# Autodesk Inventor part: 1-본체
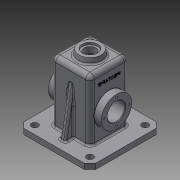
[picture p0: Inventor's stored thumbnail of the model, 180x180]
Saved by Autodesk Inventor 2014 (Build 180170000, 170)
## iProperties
Created: 2016-02
Part Number: 1-본체
Material: 일반
Document SubType Name: Modeling
Designer: Administrator
Density: 1 g/cm^3
Appearance: 기본값
Author: Administrator
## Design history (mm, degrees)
node "작업 평면1"
sketch "스케치1"
  geometry: L1 (-65, 65)-(65, 65); L2 (65, 65)-(65, -65); L3 (65, -65)-(-65, -65); L4 (-65, -65)-(-65, 65); 3 further points
  constraints: 8 end point, 2 midpoint, 2 parallel, 1 horizontal, 1 horizontal alignment, 1 perpendicular, 1 vertical alignment
  dimensions: "d1" = 130 distance of L1.start L1.end; "d2" = 130 distance of L1.end L2.end
extrude "돌출1" new body sketch "스케치1" distance "d3" = 10; taper "d4" = 0 deg
sketch "스케치2"
  geometry: L1 (-35, 35)-(35, 35); L2 (35, 35)-(35, -35); L3 (35, -35)-(-35, -35); L4 (-35, -35)-(-35, 35); L5 (30, 30)-(-30, 30); L6 (-30, 30)-(-30, -30); L7 (-30, -30)-(30, -30); L8 (30, -30)-(30, 30); 3 further points
  constraints: 16 end point, 4 parallel, 3 perpendicular, 2 midpoint, 1 horizontal, 1 horizontal alignment, 1 vertical alignment, 3 other
  dimensions: "d5" = 70 distance of L1.start L1.end; "d8" = 5 distance between parallel lines of L2 L8
extrude "돌출2" join sketch "스케치2" distance "d6" = 120; taper "d7" = 0 deg
extrude "돌출3" cut sketch "스케치2" distance "d9" = 115; taper "d10" = 0 deg
sketch "스케치3"
  geometry: C1 r 27.5 at (0, 0); 1 further point
  constraints: 1 centre point, 1 coincident
  dimensions: "d11" = 55 diameter of C1
extrude "돌출4" join sketch "스케치3" stored distance "d12" = 96; taper "d13" = 0 deg
hole "구멍1" diameter "d16" = 32; stored, may be unused: countersink angle "d20" = 90 deg, drill point angle "d22" = 118 deg; dims "d14" = 10, "d15" = 10, "d17" = 6, "d18" = 4, "d19" = 2, "d21" = 8
sketch "스케치6" dims "d32" = 45
  geometry: 3 further points
  constraints: 2 horizontal alignment, 1 coincident, 2 other
hole "구멍2" sketch "스케치6" at (-22.5, 0) diameter "d33" = 3.242; stored, may be unused: countersink angle "d37" = 90 deg, drill point angle "d39" = 118 deg; dims "d34" = 8, "d35" = 4, "d36" = 2, "d38" = 10
sketch "스케치4"
  geometry: L1 (30, -55)-(30, 60) reference; L2 (-30, -55)-(-30, 60) reference; L3 (30, 27.5)-(-30, 27.5); L4 (-30, 27.5)-(-23, 20.5); L5 (-23, 20.5)-(-23, 0); L6 (-23, 0)-(23, 0); L7 (23, 0)-(23, 20.5); L8 (23, 20.5)-(30, 27.5); 2 further points
  constraints: 12 end point, 4 perpendicular, 2 point on line, 1 coincident, 1 midpoint
  dimensions: "d23" = 135 deg angle of L1 L8; "d24" = 135 deg angle of L2 L4; "d25" = 7 distance between parallel lines of L7 L1; "d26" = 55 diameter of L3 L6
revolve "회전1" sketch "스케치4" stored, may be unused: angle "d27" = 90 deg
node "작업 평면2"
sketch "스케치5"
  geometry: C1 r 20 at (0, 0); 1 further point
  constraints: 1 centre point, 1 coincident
  dimensions: "d29" = 40 diameter of C1
extrude "돌출5" join sketch "스케치5" stored distance "d30" = 96; taper "d31" = 10 deg
hole "구멍3" diameter "d45" = 21; stored, may be unused: countersink angle "d49" = 90 deg, drill point angle "d51" = 0 deg; dims "d43" = 10, "d44" = 10, "d46" = 8, "d47" = 28, "d48" = 4, "d50" = 10
sketch "스케치7"
  geometry: L1 (35, 65)-(35, -45) reference; L2 (35, -45)-(65, -45) reference; L3 (65, -45)-(65, -55) reference; L4 (65, -55)-(30, -55) reference; L5 (30, -55)-(30, 60) reference; L6 (30, 60)-(10.5, 60) reference; L7 (10.5, 60)-(10.5, 71) reference; L8 (10.5, 71)-(14, 71) reference; L9 (14, 71)-(14, 75) reference; L10 (14, 75)-(20, 75) reference; L11 (20, 75)-(21.763, 65) reference; L12 (21.763, 65)-(35, 65) reference; L13 (-30, -55)-(-65, -55) reference; L14 (-65, -55)-(-65, -45) reference; L15 (-65, -45)-(-35, -45) reference; L16 (-35, -45)-(-35, 65) reference; L17 (-35, 65)-(-21.763, 65) reference; L18 (-21.763, 65)-(-20, 75) reference; L19 (-20, 75)-(-14, 75) reference; L20 (-14, 75)-(-14, 71) reference; L21 (-14, 71)-(-10.5, 71) reference; L22 (-10.5, 71)-(-10.5, 60) reference; L23 (-10.5, 60)-(-30, 60) reference; L24 (-30, 60)-(-30, -55) reference; L25 (-50, -45)-(-35, 40.069); L26 (35, 40.069)-(50, -45); 1 further point
  constraints: 4 end point, 2 midpoint, 2 point on line
  dimensions: "d52" = 15 distance from line of L14 L25.start; "d53" = 10 deg angle of L14 L25; "d54" = 15 distance from line of L3 L26.end (= d52); "d55" = 10 deg angle of L3 L26 (= d53)
  node "절단 모서리 투영1"
feature "리브1" dims "d56" = 1, "d57" = 10, "d58" = 0, "d59" = 0, "d60" = 1, "d61" = 1
feature "리브2" dims "d62" = 1, "d63" = 10, "d64" = 0, "d65" = 0, "d66" = 1, "d67" = 1
chamfer "모따기1" distance "d68" = 10; stored, may be unused: second distance "d69" = 2, angle "d70" = 45 deg
sketch "스케치8"
  geometry: L1 (-50, -50)-(50, -50); L2 (50, -50)-(50, 50); L3 (50, 50)-(-50, 50); L4 (-50, 50)-(-50, -50); 7 further points
  constraints: 8 end point, 4 coincident, 2 midpoint, 2 parallel, 2 perpendicular, 1 horizontal, 1 horizontal alignment, 1 vertical alignment
  dimensions: "d71" = 100 distance of L3.end L1.start
hole "구멍4" sketch "스케치8" at (-50, -50), (50, -50), (50, 50), (-50, 50) diameter "d72" = 12; stored, may be unused: countersink angle "d76" = 90 deg, drill point angle "d78" = 0 deg; dims "d73" = 8, "d74" = 28, "d75" = 4, "d77" = 10
fillet "모깎기1" dims "d79" = 8
fillet "모깎기2" dims "d80" = 8
fillet "모깎기3" dims "d81" = 0.5
chamfer "모따기2" distance "d82" = 1; stored, may be unused: second distance "d83" = 2, angle "d84" = 45 deg
fillet "모깎기4" dims "d85" = 3
fillet "모깎기5" dims "d86" = 3
fillet "모깎기9" dims "d93" = 3
fillet "모깎기10" dims "d94" = 3
fillet "모깎기11" dims "d95" = 3
sketch "스케치9"
  geometry: L1 (6.365, 6.261)-(6.365, 47.739); L2 (6.365, 47.739)-(17.635, 47.739); L3 (17.635, 47.739)-(17.635, 6.261); L4 (17.635, 6.261)-(6.365, 6.261); L5 (-18, 7)-(-18, 47) reference; 3 further points
  constraints: 2 midpoint, 1 horizontal alignment, 2 other
  dimensions: "d90" = 30 distance from line of L5 point (12, 47.739)
feature "엠보싱1" sketch "스케치9" dims "d91" = 0.5, "d92" = 0
node "솔리드1"
pattern_circular "원형 패턴1" dims angle "d41" = 360 deg
mirror "대칭1"
other parameters: "d0" = -55
